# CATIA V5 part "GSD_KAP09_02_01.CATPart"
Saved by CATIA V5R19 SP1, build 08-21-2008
Part number: GSD_REPETITION_01
Description: Beispielmodell: Objekte wiederholen  Maik Hertha IT Consultants
Bounding box of the stored display mesh (mm): x -80.67 to 90.705, y 0 to 0, z 19.637 to 52.356
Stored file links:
  \GSD_BUCH_UEBUNG\GSD_KAP09_02_01.CATPart
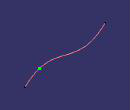
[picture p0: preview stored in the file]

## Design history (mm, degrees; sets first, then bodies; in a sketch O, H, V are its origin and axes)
AxisSystem1: origin (0, 0, 0), X (1, 0, 0), Y (0, 1, 0), Z (0, 0, 1)
Set1
  Sketch1 on ZX plane of AxisSystem1, origin (0, 0, 0), H (0, 0, 1), V (1, 0, 0)
    spline S1 through (19.6367, 90.705) (41.1927, 35.896) (30.0298, -28.9484) (52.3557, -80.6695)
  Point1: type OnCurve, Support Sketch1, Ratio 0.2
Body1 (main body)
